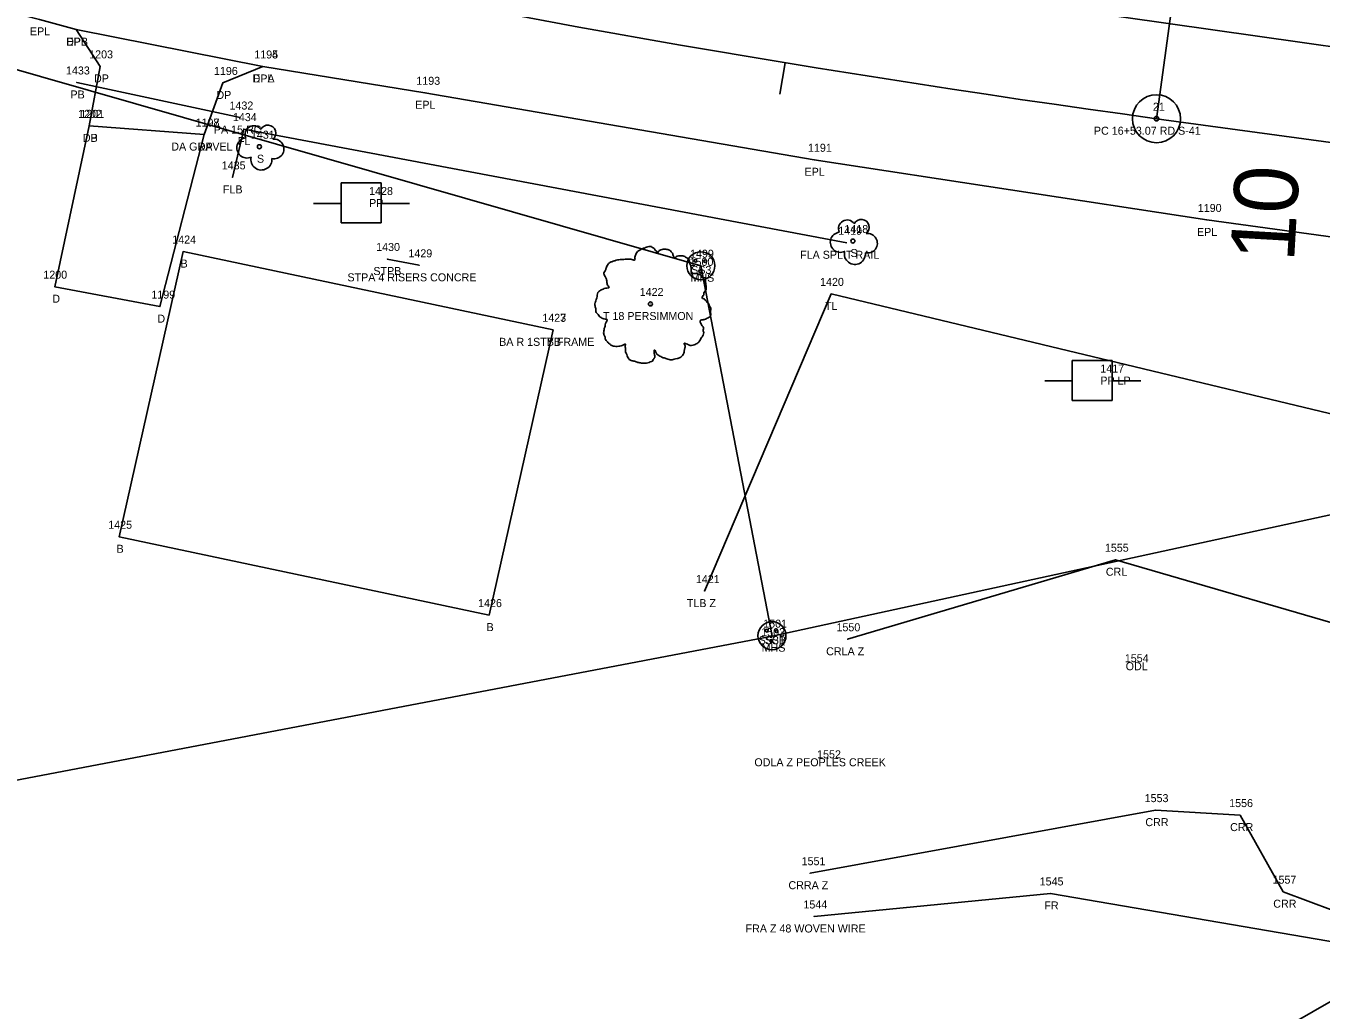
# Model space of a CAD drawing. Extents: x 1812340 to 1815011, y 1177659 to 1180159.
# Drawn here: x 1813396.9 to 1813558.8, y 1178660 to 1178783 of the extents above; entities that cross this region are included whole.
import ezdxf

# ---------------------------------------------------------------- set-up
doc = ezdxf.new("R2010")
doc.units = 0
for name, color, linetype in [('RD_EX_Bldg', 7, 'Continuous'), ('RD_EX_Bldg_txCode', 7, 'Continuous'), ('RD_EX_Conc', 7, 'Continuous'), ('RD_EX_Conc_txCode', 7, 'Continuous'), ('RD_EX_DR_Inlet', 7, 'Continuous'), ('RD_EX_DR_Pipe', 7, 'Continuous'), ('RD_EX_DR_Pipe_txCode', 7, 'Continuous'), ('RD_EX_Driveway', 7, 'Continuous'), ('RD_EX_Driveway_txCode', 7, 'Continuous'), ('RD_EX_Fence_Other', 7, 'Continuous'), ('RD_EX_Fence_Other_txCode', 7, 'Continuous'), ('RD_EX_H2O', 7, 'Continuous'), ('RD_EX_H2O_txCode', 7, 'Continuous'), ('RD_EX_Misc', 7, 'Continuous'), ('RD_EX_Road', 7, 'Continuous'), ('RD_EX_Road_txCode', 7, 'Continuous'), ('RD_EX_UT', 7, 'Continuous'), ('RD_EX_UT_txCode', 7, 'Continuous'), ('RD_EX_VEG', 7, 'Continuous'), ('RD_EX_VEG_txCode', 7, 'Continuous'), ('RD_HC_CL', 7, 'Continuous'), ('RD_HC_Data', 7, 'Continuous'), ('RD_HC_Data_Tic', 7, 'Continuous'), ('RD_HC_TX_Sta50', 7, 'Continuous'), ('RD_HC_txCode', 7, 'Continuous'), ('RD_SMD_Locator', 7, 'Continuous')]:
    doc.layers.add(name, color=color, linetype=linetype)

msp = doc.modelspace()

# ---------------------------------------------------------------- linework, layer by layer
at = {"layer": 'RD_EX_Bldg'}
msp.add_lwpolyline([(1813462.81, 1178745.04), (1813416.58, 1178754.82), (1813408.58, 1178719.18), (1813454.82, 1178709.39), (1813462.81, 1178745.04)], dxfattribs=at)
at = {"layer": 'RD_EX_Conc'}
msp.add_line((1813446.08, 1178753.1), (1813442.1, 1178753.89), dxfattribs=at)
at = {"layer": 'RD_EX_DR_Inlet'}
for centre, radius in [((1813481.28, 1178753.05), 1.75), ((1813480.62, 1178753.68), 0.175), ((1813481.19, 1178752.38), 0.175), ((1813481.84, 1178753.61), 0.175), ((1813490.17, 1178706.82), 1.75), ((1813489.51, 1178707.45), 0.175), ((1813490.73, 1178707.38), 0.175), ((1813490.09, 1178706.16), 0.175)]:
    msp.add_circle(centre, radius, dxfattribs=at)
at = {"layer": 'RD_EX_DR_Pipe'}
msp.add_line((1813423.73, 1178771.57), (1813403.29, 1178775.95), dxfattribs=at)
at = {"layer": 'RD_EX_Driveway'}
for points in [[(1813426.54, 1178777.95), (1813421.53, 1178775.89), (1813419.21, 1178769.44), (1813404.84, 1178770.53), (1813406.23, 1178777.96), (1813403.21, 1178782.55)], [(1813419.21, 1178769.44), (1813413.68, 1178747.94), (1813400.54, 1178750.43), (1813404.84, 1178770.53)]]:
    msp.add_lwpolyline(points, dxfattribs=at)
at = {"layer": 'RD_EX_Fence_Other'}
for points in [[(1813499.51, 1178755.92), (1813424.16, 1178770.12), (1813422.76, 1178764.09)], [(1813495.44, 1178671.73), (1813524.97, 1178674.61), (1813567.3, 1178667.34), (1813625.77, 1178659.53), (1813676.75, 1178657.94), (1813689.16, 1178653.47)]]:
    msp.add_lwpolyline(points, dxfattribs=at)
at = {"layer": 'RD_EX_H2O'}
for points in [[(1813499.62, 1178706.37), (1813533.11, 1178716.31), (1813566.87, 1178706.45), (1813581.02, 1178703.79), (1813602.73, 1178697.66), (1813630.18, 1178688.94), (1813658.74, 1178690.22), (1813683.52, 1178690.56), (1813733.77, 1178695.63), (1813767.86, 1178725.16), (1813778.94, 1178729.95)], [(1813494.93, 1178677.14), (1813538.08, 1178685.02), (1813548.67, 1178684.4), (1813554.06, 1178674.83), (1813572.78, 1178667.8), (1813599.8, 1178663.18), (1813623.26, 1178662.12), (1813655.35, 1178662.6), (1813687.65, 1178668.53), (1813720.68, 1178667.78), (1813740.16, 1178669.89), (1813749.02, 1178672.08), (1813765.42, 1178660.89)]]:
    msp.add_lwpolyline(points, dxfattribs=at)
at = {"layer": 'RD_EX_Misc'}
msp.add_lwpolyline([(1813405.71, 1178572.74), (1813779.17, 1178786.7), (1813799.35, 1179222.21)], dxfattribs=at)
at = {"layer": 'RD_EX_Road'}
for points in [[(1813668.47, 1179045.78), (1813666.19, 1178996.77), (1813663.63, 1178947.81), (1813660.91, 1178900.64), (1813659.53, 1178882.12), (1813657.19, 1178859.48), (1813656.91, 1178851.42), (1813653.67, 1178829.82), (1813648.43, 1178809.53), (1813642.94, 1178796.31), (1813638.42, 1178791.25), (1813631.39, 1178785.04), (1813613.59, 1178777.71), (1813596.09, 1178775.31), (1813522.62, 1178785.74), (1813518.21, 1178785.19), (1813499.47, 1178787.87), (1813450.56, 1178796.06), (1813414.35, 1178802.92), (1813398.64, 1178806.42), (1813355.44, 1178817.13)], [(1813732.94, 1178707.95), (1813689.88, 1178731.75), (1813641.71, 1178744.36), (1813593.37, 1178752.09), (1813544.49, 1178758.77), (1813495.45, 1178766.29), (1813446.8, 1178774.66), (1813426.54, 1178777.95), (1813403.21, 1178782.55), (1813398.65, 1178783.84), (1813350.68, 1178796.09), (1813343.23, 1178797.92), (1813318.7, 1178804.23), (1813303.26, 1178808.85), (1813256.8, 1178823.17), (1813209.81, 1178838.91), (1813163.27, 1178855.57)]]:
    msp.add_lwpolyline(points, dxfattribs=at)
at = {"layer": 'RD_EX_UT'}
for p, q in [((1813441.32, 1178763.4), (1813436.32, 1178763.4)), ((1813436.32, 1178763.4), (1813436.32, 1178758.4)), ((1813441.32, 1178758.4), (1813441.32, 1178763.4)), ((1813432.89, 1178760.83), (1813436.36, 1178760.83)), ((1813441.25, 1178760.83), (1813444.89, 1178760.83)), ((1813436.32, 1178758.4), (1813441.32, 1178758.4)), ((1813532.69, 1178741.21), (1813527.69, 1178741.21)), ((1813527.69, 1178741.21), (1813527.69, 1178736.21)), ((1813532.69, 1178736.21), (1813532.69, 1178741.21)), ((1813524.26, 1178738.65), (1813527.73, 1178738.65)), ((1813532.62, 1178738.65), (1813536.26, 1178738.65)), ((1813527.69, 1178736.21), (1813532.69, 1178736.21))]:
    msp.add_line(p, q, dxfattribs=at)
for points in [[(1812996.89, 1178919.95), (1813204.49, 1178832.44), (1813481.3, 1178753.03), (1813490.2, 1178706.76)], [(1813817.45, 1178777.9), (1813490.2, 1178706.76), (1813294.33, 1178669.42)]]:
    msp.add_lwpolyline(points, dxfattribs=at)
at = {"layer": 'RD_EX_VEG'}
msp.add_lwpolyline([(1813615.69, 1178721.17), (1813497.56, 1178749.53), (1813481.72, 1178712.39)], dxfattribs=at)
for centre, radius in [((1813426.12, 1178767.92), 0.25), ((1813500.28, 1178756.14), 0.25), ((1813474.98, 1178748.27), 0.25), ((1813474.97, 1178748.25), 0.0001)]:
    msp.add_circle(centre, radius, dxfattribs=at)
for centre, radius, start, end in [((1813425.4, 1178769.47), 1.08, 34.9763, 204.756), ((1813427.17, 1178769.63), 0.995, 308.7626, 152.0467), ((1813424.56, 1178767.77), 1.26, 96.4518, 294.734), ((1813427.96, 1178767.64), 1.22, 256.5667, 98.1046), ((1813426.37, 1178766.33), 1.32, 166.8827, 5.7589), ((1813499.56, 1178757.69), 1.08, 34.9763, 204.756), ((1813501.33, 1178757.84), 0.995, 308.7626, 152.0467), ((1813498.72, 1178755.98), 1.26, 96.4518, 294.734), ((1813502.12, 1178755.86), 1.22, 256.5667, 98.1046), ((1813500.53, 1178754.54), 1.32, 166.8827, 5.7589)]:
    msp.add_arc(centre, radius, start, end, dxfattribs=at)
for points in [[(1813475.11, 1178755.44), (1813474.81, 1178755.46), (1813474.49, 1178755.36), (1813474.24, 1178755.26), (1813474.02, 1178755.19), (1813473.79, 1178755.09), (1813473.49, 1178754.91), (1813473.27, 1178754.71), (1813473.14, 1178754.46), (1813473.09, 1178754.24), (1813473.04, 1178753.96), (1813473.04, 1178753.79), (1813472.92, 1178753.76), (1813472.77, 1178753.79), (1813472.52, 1178753.86), (1813472.27, 1178753.86), (1813472.02, 1178753.86), (1813471.67, 1178753.84), (1813471.32, 1178753.84), (1813471.04, 1178753.79), (1813470.72, 1178753.74), (1813470.34, 1178753.61), (1813469.99, 1178753.49), (1813469.69, 1178753.24), (1813469.44, 1178752.76), (1813469.32, 1178752.41), (1813469.17, 1178752.16), (1813469.32, 1178751.72), (1813469.49, 1178751.37), (1813469.52, 1178751.17), (1813469.59, 1178750.74), (1813469.69, 1178750.52), (1813469.82, 1178750.32), (1813469.74, 1178750.29), (1813469.37, 1178750.24), (1813469.07, 1178750.14), (1813468.64, 1178749.92), (1813468.42, 1178749.69), (1813468.32, 1178749.37), (1813468.29, 1178749.02), (1813468.19, 1178748.82), (1813468.12, 1178748.54), (1813468.09, 1178748.47), (1813468.04, 1178748.14), (1813468.14, 1178747.69), (1813468.17, 1178747.34), (1813468.29, 1178747.12), (1813468.44, 1178746.94), (1813468.62, 1178746.69), (1813469.02, 1178746.47), (1813469.34, 1178746.37), (1813469.54, 1178746.34), (1813469.37, 1178745.84), (1813469.32, 1178745.49), (1813469.19, 1178745.09), (1813469.19, 1178745.02), (1813469.14, 1178744.54), (1813469.29, 1178744.22), (1813469.37, 1178743.84), (1813469.54, 1178743.62), (1813469.82, 1178743.32), (1813470.14, 1178743.09), (1813470.64, 1178742.97), (1813471.04, 1178742.99), (1813471.62, 1178743.17), (1813471.87, 1178743.24), (1813471.84, 1178743.07), (1813471.87, 1178742.69), (1813471.87, 1178742.27), (1813472.02, 1178741.94), (1813472.12, 1178741.67), (1813472.27, 1178741.42), (1813472.59, 1178741.19), (1813472.99, 1178741.12), (1813473.42, 1178740.97), (1813473.87, 1178740.89), (1813474.36, 1178740.87), (1813474.96, 1178741.02), (1813475.24, 1178741.14), (1813475.34, 1178741.32), (1813475.54, 1178741.69), (1813475.49, 1178741.92), (1813475.51, 1178742.52), (1813475.61, 1178742.34), (1813475.79, 1178741.99), (1813476.29, 1178741.69), (1813476.69, 1178741.52), (1813477.16, 1178741.37), (1813477.46, 1178741.29), (1813477.94, 1178741.37), (1813478.31, 1178741.44), (1813478.69, 1178741.57), (1813478.99, 1178741.84), (1813479.16, 1178742.12), (1813479.21, 1178742.39), (1813479.29, 1178742.77), (1813479.34, 1178742.94)], [(1813479.34, 1178742.94), (1813479.26, 1178743.12), (1813479.21, 1178743.37), (1813479.29, 1178743.34), (1813479.46, 1178743.29), (1813479.74, 1178743.17), (1813479.96, 1178743.09), (1813480.29, 1178743.12), (1813480.56, 1178743.22), (1813481.01, 1178743.49), (1813481.29, 1178743.97), (1813481.56, 1178744.37), (1813481.64, 1178744.69), (1813481.59, 1178744.92), (1813481.56, 1178745.42), (1813481.36, 1178745.67), (1813481.31, 1178745.79), (1813481.21, 1178746.19), (1813481.29, 1178746.24), (1813481.56, 1178746.29), (1813481.94, 1178746.42), (1813482.21, 1178746.54), (1813482.44, 1178746.72), (1813482.51, 1178746.94), (1813482.49, 1178747.34), (1813482.54, 1178747.74), (1813482.46, 1178747.89), (1813482.36, 1178748.04), (1813482.29, 1178748.24), (1813482.14, 1178748.39), (1813482.04, 1178748.54), (1813481.94, 1178748.64), (1813481.81, 1178748.79), (1813481.64, 1178748.92), (1813481.49, 1178748.97), (1813481.44, 1178749.12), (1813481.59, 1178749.32), (1813481.64, 1178749.42), (1813481.66, 1178749.64), (1813481.89, 1178749.99), (1813481.94, 1178750.39), (1813481.89, 1178750.82), (1813481.84, 1178751.09), (1813481.69, 1178751.37), (1813481.49, 1178751.62), (1813481.36, 1178751.79), (1813481.19, 1178751.92), (1813480.86, 1178752.04), (1813480.61, 1178752.09), (1813480.26, 1178752.09), (1813480.06, 1178752.14), (1813480.09, 1178752.19), (1813480.09, 1178752.34), (1813480.09, 1178752.61), (1813480.01, 1178753.06), (1813479.86, 1178753.56), (1813479.86, 1178753.59), (1813479.76, 1178753.84), (1813479.54, 1178754.04), (1813479.36, 1178754.14), (1813479.16, 1178754.26), (1813478.91, 1178754.29), (1813478.61, 1178754.29), (1813478.34, 1178754.24), (1813478.14, 1178754.14), (1813477.96, 1178754.01), (1813477.89, 1178754.16), (1813477.79, 1178754.46), (1813477.74, 1178754.61), (1813477.59, 1178754.79), (1813477.36, 1178754.99), (1813476.91, 1178755.11), (1813476.29, 1178755.04), (1813475.99, 1178754.84), (1813475.84, 1178754.66), (1813475.79, 1178754.79), (1813475.59, 1178754.99), (1813475.49, 1178755.16), (1813475.31, 1178755.29), (1813475.16, 1178755.39), (1813475.06, 1178755.44)]]:
    msp.add_spline(points, degree=3, dxfattribs=at)
at = {"layer": 'RD_HC_CL'}
msp.add_line((1813641.28, 1178757.34), (1813538.22, 1178771.42), dxfattribs=at)
msp.add_arc((1813766.93, 1180445.18), 1689.31, 243.58271, 262.2191, dxfattribs=at)
at = {"layer": 'RD_HC_Data'}
msp.add_line((1813538.22, 1178771.42), (1813554.02, 1178887.04), dxfattribs=at)
for radius in [3, 0.282]:
    msp.add_circle((1813538.22, 1178771.42), radius, dxfattribs=at)
at = {"layer": 'RD_HC_Data_Tic'}
msp.add_line((1813491.82, 1178778.42), (1813491.17, 1178774.47), dxfattribs=at)
at = {"layer": 'RD_SMD_Locator'}
for centre in [(1813403.21, 1178782.55), (1813403.21, 1178782.55), (1813406.23, 1178777.96), (1813426.54, 1178777.95), (1813426.54, 1178777.95), (1813403.29, 1178775.95), (1813421.53, 1178775.89), (1813446.8, 1178774.66), (1813404.84, 1178770.53), (1813404.84, 1178770.53), (1813423.73, 1178771.57), (1813538.22, 1178771.42), (1813419.21, 1178769.44), (1813419.21, 1178769.44), (1813424.16, 1178770.12), (1813495.45, 1178766.29), (1813422.76, 1178764.09), (1813544.49, 1178758.77), (1813499.51, 1178755.92), (1813416.58, 1178754.82), (1813442.1, 1178753.89), (1813446.08, 1178753.1), (1813481.3, 1178753.03), (1813400.54, 1178750.43), (1813497.56, 1178749.53), (1813413.68, 1178747.94), (1813462.81, 1178745.04), (1813462.81, 1178745.04), (1813408.58, 1178719.18), (1813533.11, 1178716.31), (1813481.72, 1178712.39), (1813454.82, 1178709.39), (1813490.2, 1178706.76), (1813490.2, 1178706.76), (1813499.62, 1178706.37), (1813535.61, 1178703.5), (1813497.15, 1178691.5), (1813538.08, 1178685.02), (1813548.67, 1178684.4), (1813494.93, 1178677.14), (1813554.06, 1178674.83), (1813524.97, 1178674.61), (1813495.44, 1178671.73)]:
    msp.add_circle(centre, 0.001, dxfattribs=at)

# ---------------------------------------------------------------- texts
at = {"layer": 'RD_EX_Bldg_txCode'}
for s, p in [('1424', (1813415.23, 1178755.82)), ('B', (1813416.27, 1178752.82)), ('1423', (1813461.47, 1178746.04)), ('1427', (1813461.47, 1178746.04)), ('BA R 1STY FRAME', (1813456.08, 1178743.04)), ('BB', (1813462.03, 1178743.04)), ('1425', (1813407.23, 1178720.18)), ('B', (1813408.27, 1178717.18)), ('1426', (1813453.45, 1178710.39)), ('B', (1813454.51, 1178707.39))]:
    msp.add_text(s, height=1, dxfattribs=at).set_placement(p)
at = {"layer": 'RD_EX_Conc_txCode'}
for s, p in [('1430', (1813440.71, 1178754.89)), ('1429', (1813444.74, 1178754.1)), ('STPB', (1813440.36, 1178751.89)), ('STPA 4 RISERS CONCRE', (1813437.12, 1178751.1))]:
    msp.add_text(s, height=1, dxfattribs=at).set_placement(p)
at = {"layer": 'RD_EX_DR_Pipe_txCode'}
for s, p in [('1433', (1813401.95, 1178776.95)), ('PB', (1813402.51, 1178773.95)), ('1432', (1813422.38, 1178772.57)), ('PA 15 RC', (1813420.43, 1178769.57))]:
    msp.add_text(s, height=1, dxfattribs=at).set_placement(p)
at = {"layer": 'RD_EX_Driveway_txCode'}
for s, p in [('DPB', (1813401.96, 1178780.55)), ('1203', (1813404.85, 1178778.96)), ('1195', (1813425.48, 1178778.95)), ('DP', (1813405.45, 1178775.96)), ('1196', (1813420.44, 1178776.89)), ('DPA', (1813425.27, 1178775.95)), ('DP', (1813420.75, 1178773.89)), ('1202', (1813403.46, 1178771.53)), ('1201', (1813403.74, 1178771.53)), ('1197', (1813418.15, 1178770.44)), ('1198', (1813418.15, 1178770.44)), ('DB', (1813404.06, 1178768.53)), ('DP', (1813404.06, 1178768.53)), ('DA GRAVEL', (1813415.11, 1178767.44)), ('DP', (1813418.43, 1178767.44)), ('1200', (1813399.12, 1178751.43)), ('D', (1813400.24, 1178748.43)), ('1199', (1813412.62, 1178748.94)), ('D', (1813413.37, 1178745.94))]:
    msp.add_text(s, height=1, dxfattribs=at).set_placement(p)
at = {"layer": 'RD_EX_Fence_Other_txCode'}
for s, p in [('1434', (1813422.81, 1178771.12)), ('FL', (1813423.43, 1178768.12)), ('1435', (1813421.42, 1178765.09)), ('FLB', (1813421.56, 1178762.09)), ('1419', (1813498.45, 1178756.92)), ('FLA SPLIT RAIL', (1813493.69, 1178753.92)), ('1545', (1813523.62, 1178675.61)), ('1544', (1813494.1, 1178672.73)), ('FR', (1813524.21, 1178672.61)), ('FRA Z 48 WOVEN WIRE', (1813486.87, 1178669.73))]:
    msp.add_text(s, height=1, dxfattribs=at).set_placement(p)
at = {"layer": 'RD_EX_H2O_txCode'}
for s, p in [('1555', (1813531.77, 1178717.31)), ('CRL', (1813531.89, 1178714.31)), ('1550', (1813498.23, 1178707.37)), ('CRLA Z', (1813496.94, 1178704.37)), ('1554', (1813534.26, 1178703.5)), ('ODL', (1813534.37, 1178702.5)), ('ODLA Z PEOPLES CREEK', (1813487.97, 1178690.5)), ('1552', (1813495.81, 1178691.5)), ('1553', (1813536.74, 1178686.02)), ('1556', (1813547.3, 1178685.4)), ('CRR', (1813536.83, 1178683.02)), ('CRR', (1813547.42, 1178682.4)), ('1551', (1813493.87, 1178678.14)), ('1557', (1813552.72, 1178675.83)), ('CRRA Z', (1813492.23, 1178675.14)), ('CRR', (1813552.81, 1178672.83))]:
    msp.add_text(s, height=1, dxfattribs=at).set_placement(p)
at = {"layer": 'RD_EX_Road_txCode'}
for s, p in [('EPL', (1813397.44, 1178781.84)), ('EPL', (1813402, 1178780.55)), ('1194', (1813425.48, 1178778.95)), ('EPL', (1813425.34, 1178775.95)), ('1193', (1813445.73, 1178775.66)), ('EPL', (1813445.59, 1178772.66)), ('1191', (1813494.67, 1178767.29)), ('EPL', (1813494.24, 1178764.29)), ('1190', (1813543.38, 1178759.77)), ('EPL', (1813543.28, 1178756.77))]:
    msp.add_text(s, height=1, dxfattribs=at).set_placement(p)
at = {"layer": 'RD_EX_UT_txCode'}
for s, p in [('1428', (1813439.83, 1178761.89)), ('PP', (1813439.83, 1178760.39)), ('1499', (1813479.93, 1178754.05)), ('1500', (1813479.87, 1178753.03)), ('SS3', (1813480.07, 1178752.03)), ('MHS', (1813479.99, 1178751.05)), ('1417', (1813531.2, 1178739.7)), ('PP LP', (1813531.2, 1178738.2)), ('1501', (1813489.07, 1178707.82)), ('1502', (1813488.82, 1178706.76)), ('1503', (1813488.82, 1178706.76)), ('SS3B', (1813488.5, 1178705.76)), ('MHS', (1813488.88, 1178704.82)), ('SS1', (1813489.26, 1178705.76))]:
    msp.add_text(s, height=1, dxfattribs=at).set_placement(p)
at = {"layer": 'RD_EX_VEG_txCode'}
for s, p in [('1431', (1813425.06, 1178768.92)), ('S', (1813425.81, 1178765.92)), ('1418', (1813499.22, 1178757.14)), ('S', (1813499.98, 1178754.14)), ('1420', (1813496.18, 1178750.53)), ('1422', (1813473.64, 1178749.27)), ('TL', (1813496.79, 1178747.53)), ('T 18 PERSIMMON', (1813469.05, 1178746.27)), ('1421', (1813480.66, 1178713.39)), ('TLB Z', (1813479.53, 1178710.39))]:
    msp.add_text(s, height=1, dxfattribs=at).set_placement(p)
at = {"layer": 'RD_HC_TX_Sta50'}
msp.add_text('10', height=8, rotation=86.7565, dxfattribs=at).set_placement((1813555.4, 1178753.44))
at = {"layer": 'RD_HC_txCode'}
for s, p in [('21', (1813537.77, 1178772.42)), ('PC 16+53.07 RD S-41', (1813530.4, 1178769.42))]:
    msp.add_text(s, height=1, dxfattribs=at).set_placement(p)

doc.saveas('drawing.dxf')
